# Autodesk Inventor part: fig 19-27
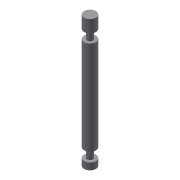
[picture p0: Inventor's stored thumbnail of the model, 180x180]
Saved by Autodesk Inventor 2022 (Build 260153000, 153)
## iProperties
Created: 2013-07
Part Number: fig 19-27
Material: Generic
Document SubType Name: Modeling
Designer: CADCIM
Density: 1 g/cm^3
Appearance: Default
Author: CADCIM
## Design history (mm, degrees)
sketch "Sketch3"
  geometry: L1 (0, 19.325)-(1.664, 19.325); L2 (1.664, 19.325)-(1.664, 15.806); L3 (1.664, 15.806)-(0.832, 15.806); L4 (0.832, 15.806)-(0.832, 13.31); L5 (0.832, 13.31)-(1.664, 13.31); L6 (1.664, 13.31)-(1.664, -13.31); L7 (1.664, -13.31)-(0.832, -13.31); L8 (0.832, -13.31)-(0.832, -15.934); L9 (0.832, -15.934)-(1.664, -15.934); L10 (1.664, -15.934)-(1.664, -17.853); L11 (1.664, -17.853)-(0, -17.853); L12 (0, -17.853)-(0, 19.325); 1 further point
  constraints: 24 end point, 8 perpendicular, 6 point on line, 1 horizontal
revolve "Revolution1" sketch "Sketch3" stored, may be unused: angle "d8" = 90 deg
body "Solid2"
